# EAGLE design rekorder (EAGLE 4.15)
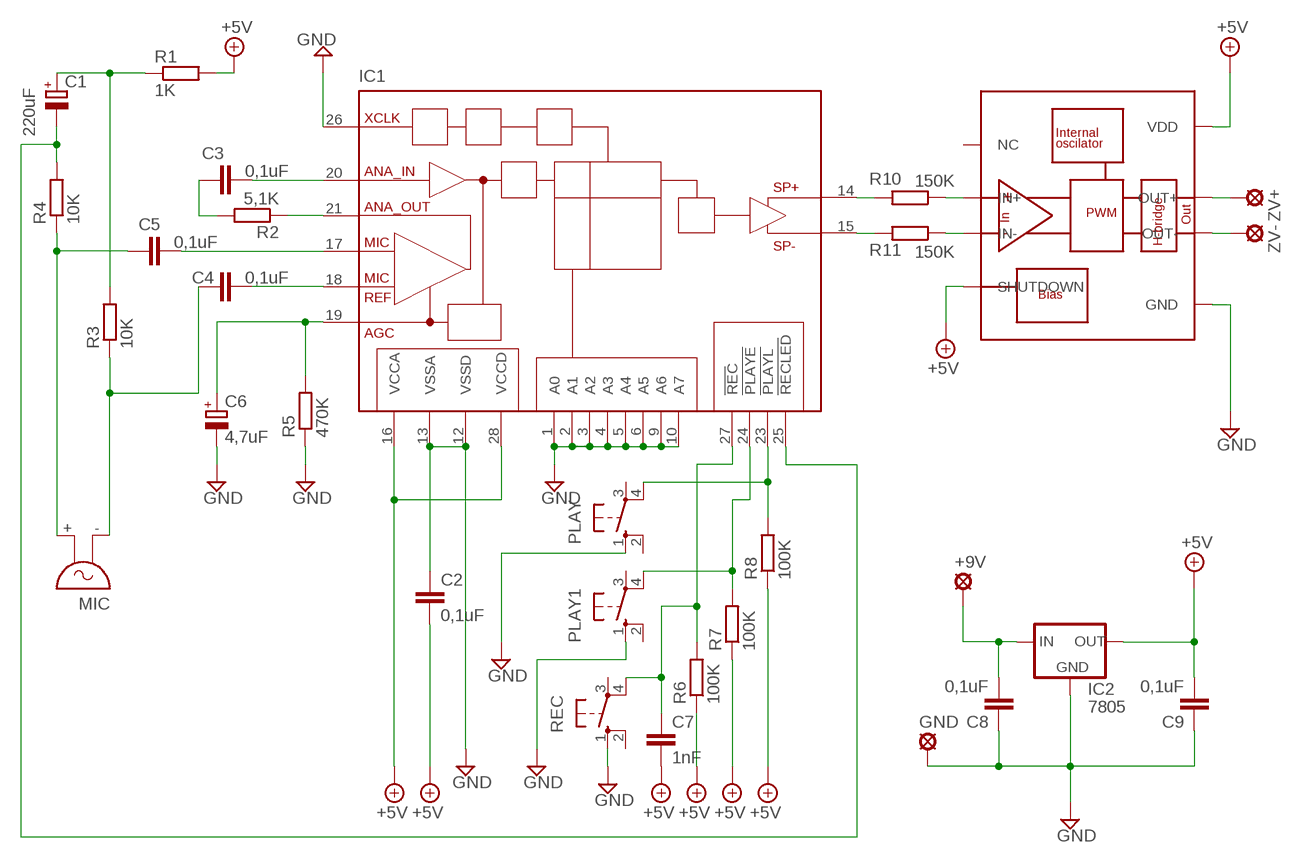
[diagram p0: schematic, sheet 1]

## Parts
+9V  SE13  [SE13]
C1  220uF  CPOL-EUE3.5-8  [E3,5-8]
C2  0,1uF  C-EUC1206  [C1206]
C3  0,1uF  C-EUC1206  [C1206]
C4  0,1uF  C-EUC1206  [C1206]
C5  0,1uF  C-EUC1206  [C1206]
C6  4,7uF  CPOL-EUE2-5  [E2-5]
C7  1nF  C-EUC1206  [C1206]
C8  0,1uF  C-EUC1206  [C1206]
C9  0,1uF  C-EUC1206  [C1206]
GND  SE13  [SE13]
IC1  ISD1400D  [DIL28-6]
IC2  7805  78XXS  [78XXS]
MIC  F/QMX  [F/QMX]
PLAY  10-XX  [B3F-10XX]
PLAY1  10-XX  [B3F-10XX]
R1  1K  R-EU_M1206  [M1206]
R2  5,1K  R-EU_M1206  [M1206]
R3  10K  R-EU_M1206  [M1206]
R4  10K  R-EU_M1206  [M1206]
R5  470K  R-EU_M1206  [M1206]
R6  100K  R-EU_M1206  [M1206]
R7  100K  R-EU_M1206  [M1206]
R8  100K  R-EU_M1206  [M1206]
R10  150K  R-EU_M1206  [M1206]
R11  150K  R-EU_M1206  [M1206]
REC  10-XX  [B3F-10XX]
U$1  TPA2005D1  [8-PIN-QFN]
ZV+  SE13  [SE13]
ZV-  SE13  [SE13]

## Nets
+5V: C2.2 C7.2 C9.2 IC1.16(VCCA) IC1.28(VCCD) IC2.OUT R1.2 R6.1 R7.1 R8.1 U$1.P$1(SHUTDOWN) U$1.P$6(VDD)
GND: C2.1 C6.- C8.1 C9.1 GND.MP IC1.1(A0) IC1.2(A1) IC1.3(A2) IC1.4(A3) IC1.5(A4) IC1.6(A5) IC1.9(A6) IC1.10(A7) IC1.12(VSSD) IC1.13(VSSA) IC1.26(XCLK) IC2.GND PLAY1.1(S) PLAY.1(S) R5.1 REC.1(S) U$1.P$7(GND)
N$1: R10.1 U$1.P$3(IN+)
N$3: IC1.14(SP+) R10.2
N$4: IC1.15(SP-) R11.2
N$5: C1.+ R1.1 R3.2
N$6: IC1.24(PLAYE) PLAY1.4(P1) R7.2
N$7: C7.1 IC1.27(REC) R6.2 REC.4(P1)
N$8: C1.- IC1.25(RECLED) R4.2
N$9: R11.1 U$1.P$4(IN-)
N$10: C3.2 IC1.20(ANA_IN)
N$11: IC1.23(PLAYL) PLAY.4(P1) R8.2
N$12: IC1.21(ANA_OUT) R2.1
N$13: C3.1 R2.2
N$14: C6.+ IC1.19(AGC) R5.2
N$15: U$1.P$5(OUT+) ZV+.MP
N$16: C5.2 IC1.17(MIC)
N$17: C4.2 IC1.18(MIC_REF)
N$18: C5.1 MIC.+ R4.1
N$19: C4.1 MIC.- R3.1
N$20: U$1.P$8(OUT-) ZV-.MP
N$21: +9V.MP C8.2 IC2.IN
Unconnected: IC1.7(NC) IC1.8(NC) IC1.11(NC) IC1.22(NC) PLAY1.2(S1) PLAY1.3(P) PLAY.2(S1) PLAY.3(P) REC.2(S1) REC.3(P) U$1.P$2(NC)

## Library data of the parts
+9V GND ZV+ ZV- = solpad:SE13: SOLDER PAD
C1 C6 = rcl:CPOL-EU: POLARIZED CAPACITOR, European symbol
C2-C5 C7-C9 = rcl:C-EU: CAPACITOR, European symbol
IC1 = isd:ISD1400D: VOICE RECORDER
IC2 = v-reg:78XXS: VOLTAGE REGULATOR
MIC = buzzer:F/QMX: BUZZER
PLAY PLAY1 REC = switch-omron:10-XX: OMRON SWITCH
R1-R8 R10 R11 = rcl:R-EU_: RESISTOR, European symbol
U$1 = texas_pp:TPA2005D1

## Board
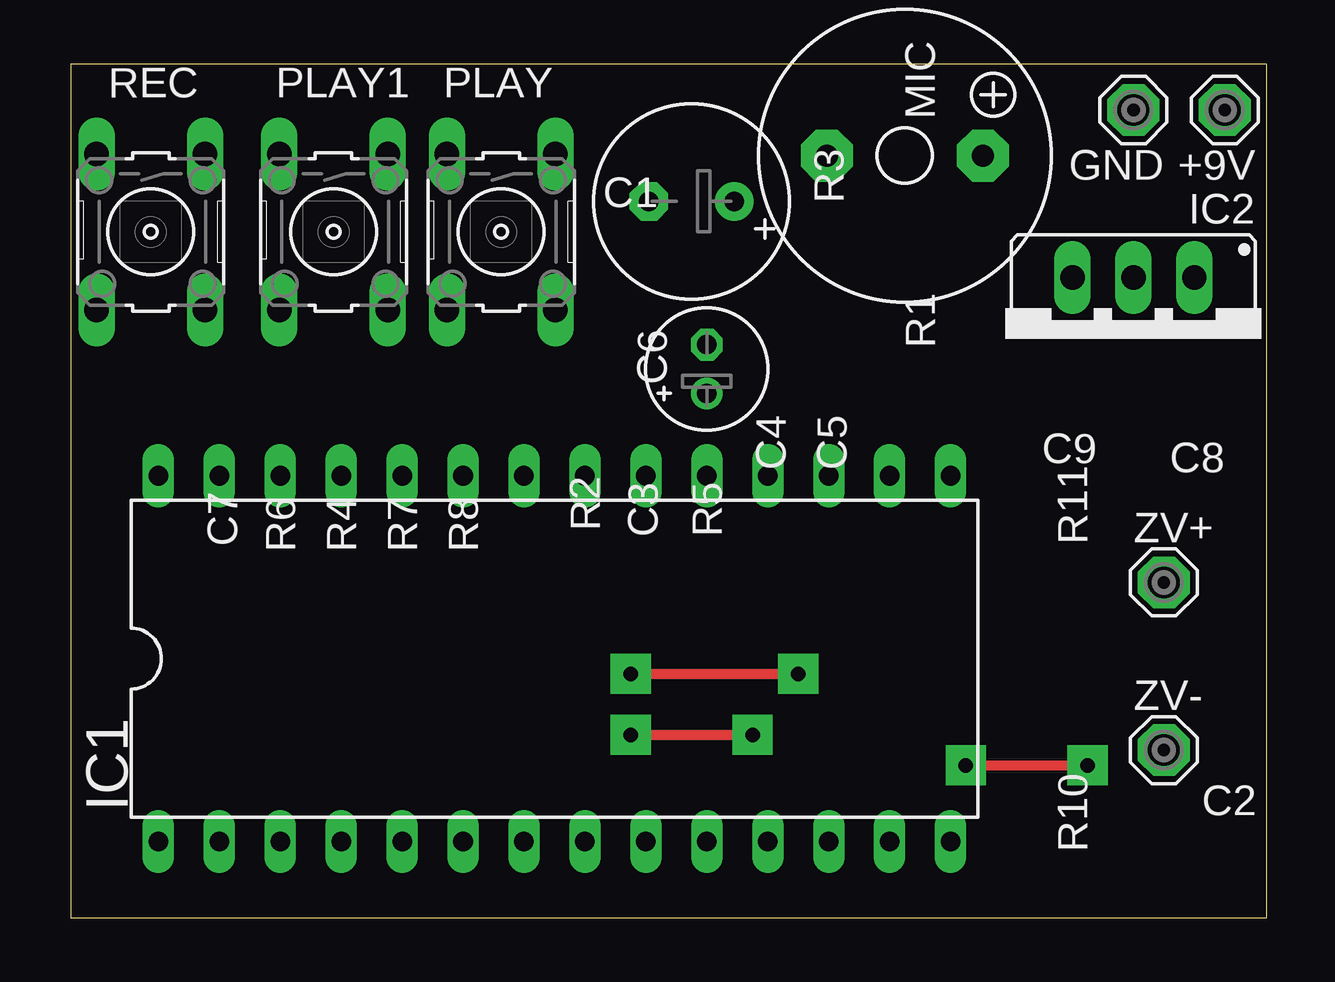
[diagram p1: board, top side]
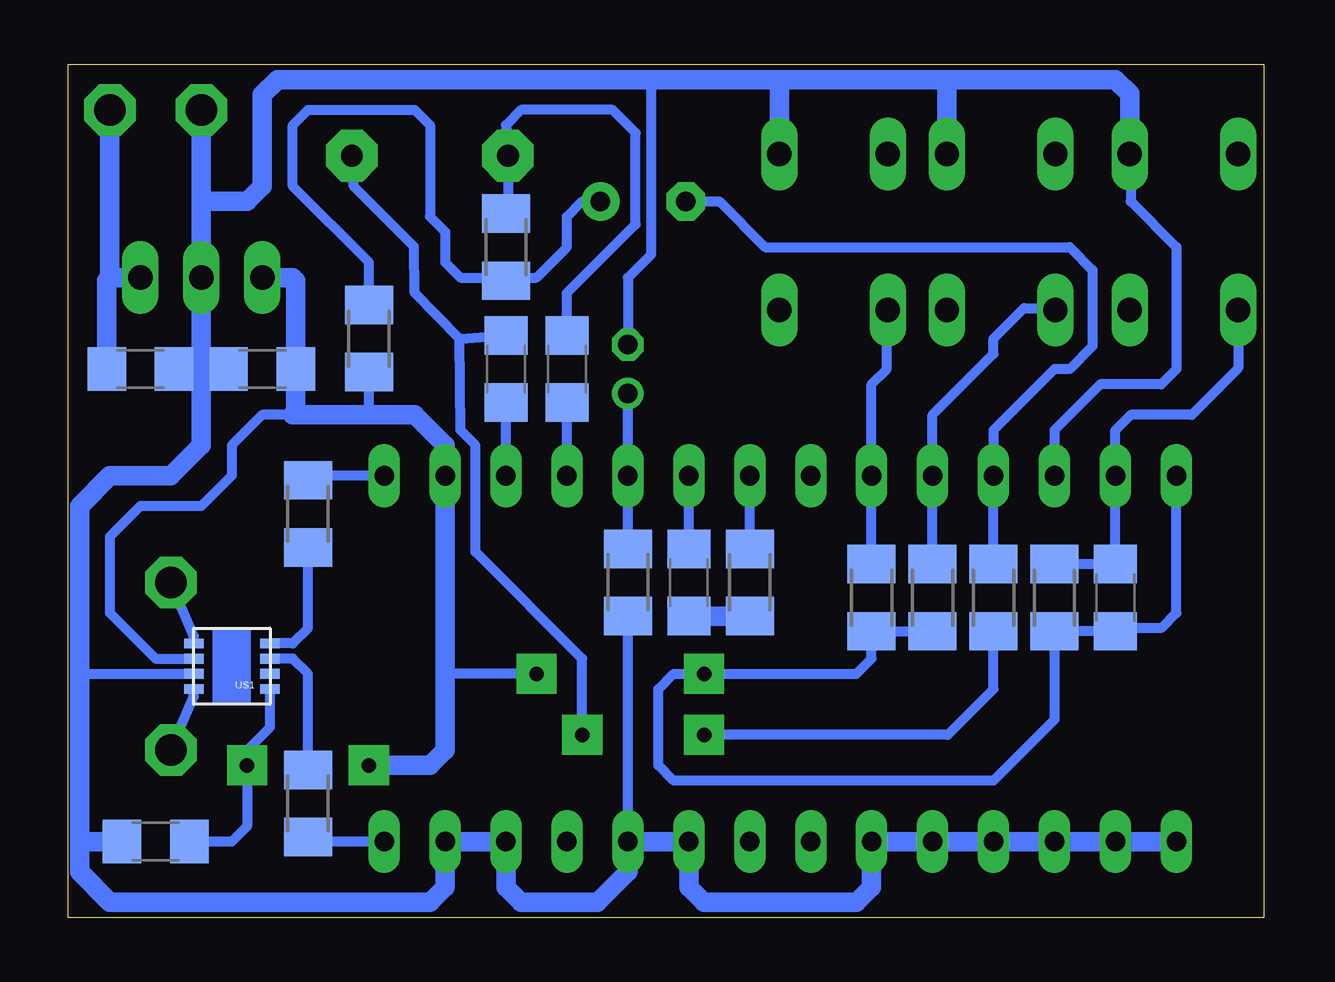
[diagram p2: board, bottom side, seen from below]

Size 49.84 x 35.55 mm. Coordinates in mm from the lower left corner, seen from the top.
Outline: 0,0 49.84,0 49.84,35.55 0,35.55 0,0
Copper layers (1*16): Top 0.035mm / dielectric 1.5mm / Bottom 0.035mm
Design rules "default": minimum track width 10mil, minimum drill 24mil, track to track 8mil, track to pad 8mil, pad to pad 8mil, via to via 8mil, smd to smd 8mil, copper to edge 40mil, drill to drill 8mil, minimum pad ring 10mil, minimum via ring 8mil, stop-mask expansion 4mil, vias tented up to drill 0mil, thermal gap 10mil

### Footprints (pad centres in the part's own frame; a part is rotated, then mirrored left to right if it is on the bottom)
SE13 = drill 1.321 pad 2.159 octagon: MP 0,0
E3,5-8 = drill 0.813 pad 1.6 round: + -1.778,0 | drill 0.813 pad 1.6 octagon: - 1.778,0
C1206 = smd 1.6 x 1.8: 1 -1.4,0; 2 1.4,0
E2-5 = drill 0.813 pad 1.27 round: + -1.016,0 | drill 0.813 pad 1.27 octagon: - 1.016,0
DIL28-6 = drill 0.813 long: 1 -16.51,-7.62; 2 -13.97,-7.62; 3 -11.43,-7.62; 4 -8.89,-7.62; 5 -6.35,-7.62; 6 -3.81,-7.62; 7 -1.27,-7.62; 8 1.27,-7.62; 9 3.81,-7.62; 10 6.35,-7.62; 11 8.89,-7.62; 12 11.43,-7.62; 13 13.97,-7.62; 14 16.51,-7.62; 15 16.51,7.62; 16 13.97,7.62; 17 11.43,7.62; 18 8.89,7.62; 19 6.35,7.62; 20 3.81,7.62; 21 1.27,7.62; 22 -1.27,7.62; 23 -3.81,7.62; 24 -6.35,7.62; 25 -8.89,7.62; 26 -11.43,7.62; 27 -13.97,7.62; 28 -16.51,7.62
78XXS = drill 1.016 long: GND 0,-2.54; IN -2.54,-2.54; OUT 2.54,-2.54
F/QMX = drill 0.914 pad 2.159 octagon: + 3.251,0; - -3.251,0
B3F-10XX = drill 1.016 long: 1 -3.251,2.261; 2 3.251,2.261; 3 -3.251,-2.261; 4 3.251,-2.261
M1206 = smd 1.6 x 2: 1 -1.4,0; 2 1.4,0
8-PIN-QFN = smd 0.813 x 0.406: P$1 -1.587,0.953; P$2 -1.587,0.318; P$3 -1.587,-0.318; P$4 -1.587,-0.953; P$5 1.587,-0.953; P$6 1.587,-0.318; P$7 1.587,0.318; P$8 1.587,0.953

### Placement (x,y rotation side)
+9V  48.1,33.65 180 top
C1  25.87,29.84 180 top
C2  46.19,3.17 0 bottom
C3  23.96,13.96 90 bottom
C4  29.04,22.86 270 bottom
C5  31.58,22.86 270 bottom
C6  26.5,22.86 90 top
C7  6.18,13.33 270 bottom
C8  46.83,22.86 180 bottom
C9  41.75,22.86 0 bottom
GND  44.29,33.65 180 top
IC1  20.15,10.79 0 top
IC2  44.29,24.12 180 top
MIC  34.76,31.75 0 top
PLAY  17.93,28.57 270 top
PLAY1  10.95,28.57 270 top
R1  37.3,24.12 270 bottom
R2  21.43,13.96 270 bottom
R3  31.58,27.94 270 bottom
R4  11.27,13.33 90 bottom
R5  26.5,13.96 90 bottom
R6  8.73,13.33 90 bottom
R7  13.8,13.33 90 bottom
R8  16.34,13.33 90 bottom
R10  39.84,4.76 270 bottom
R11  39.84,16.82 90 bottom
REC  3.33,28.57 270 top
U$1  43.02,10.47 180 bottom
ZV+  45.55,13.96 0 top
ZV-  45.55,6.98 0 top

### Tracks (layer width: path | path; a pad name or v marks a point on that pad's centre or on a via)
+5V  (via drill 0.6 pad 1.68)
  Top 0.406: v37.3,6.35 v42.38,6.35 | v23.33,10.15 v30.32,10.15
  Bottom 0.406: R6.1 9.04,12.06 8.91,11.93 R6.1 | R6.1 C7.2 6.18,12.06 4.28,12.06 3.65,12.7 IC1.28 | 14.12,12.06 13.99,11.93 R7.1 R8.1 | R8.1 16.98,11.74 16.79,11.93 R8.1 | 40.35,26.54 40.48,26.67 | U$1.P$6 46.19,10.79 48.1,12.7 48.1,15.87 46.83,17.14 44.29,17.14 43.02,18.41 43.02,19.68 41.75,20.95 40.48,20.95 40.35,21.08 | U$1.P$1 41.43,7.93 42.38,6.98 v42.38,6.35 42.38,3.81 43.02,3.17 C2.2 44.92,2.54 | v30.32,10.15 34.12,10.15 | R6.1 8.73,8.25 11.27,5.71 24.6,5.71 25.23,6.35 25.23,9.52 24.6,10.15 v23.33,10.15 16.98,10.15 16.34,10.79 R8.1 | R8.1 16.34,12.06 | 36.8,22.73 R1.2 37.3,20.95
  Bottom 0.813: 40.48,26.67 IC2.OUT | 40.35,26.54 C9.2 40.35,21.08 | 40.48,20.95 37.3,20.95 35.4,20.95 34.12,19.68 IC1.16 34.12,10.15 34.12,6.98 34.76,6.35 v37.3,6.35
GND
  Bottom 0.406: 10,34.92 13.21,34.88 | IC1.10 R5.1 | C6.- 26.5,26.67 25.55,27.62 25.55,34.92 | 49.37,10.15 U$1.P$7 | 45.55,0.63 45.69,0.76 | 20.15,34.92 20.19,34.88 | REC.1 5.59,31.78 5.55,31.75 5.55,29.84 3.65,27.94 3.65,22.86 4.28,22.22 6.82,22.22 8.73,20.32 IC1.26
  Bottom 0.813: IC1.1 IC1.2 IC1.3 IC1.4 IC1.5 IC1.6 16.34,1.27 16.98,0.63 23.33,0.63 23.96,1.27 IC1.9 IC1.10 26.5,1.9 27.78,0.63 30.95,0.63 31.58,1.27 IC1.12 IC1.13 34.12,1.27 34.76,0.63 45.55,0.63 48.1,0.63 49.37,1.9 49.37,3.17 | REC.1 5.59,34.32 6.18,34.92 10,34.92 20.15,34.92 25.55,34.92 41.11,34.92 41.75,34.29 41.75,30.48 42.38,29.84 44.29,29.84 | 13.21,34.88 PLAY1.1 | 44.29,29.84 GND.MP | 44.29,29.84 IC2.GND 44.29,22.86 | 49.37,3.17 49.37,10.15 49.37,17.14 48.1,18.41 45.55,18.41 44.29,19.68 44.29,22.86 | 20.19,34.88 PLAY.1 | 44.29,22.86 C9.1 | 44.29,22.86 C8.1 | 49.37,3.17 C2.1
N$1
  Bottom 0.406: R10.1 39.84,10.15 40.48,10.79 U$1.P$3
N$3
  Bottom 0.406: R10.2 39.84,3.17 IC1.14
N$4
  Bottom 0.406: R11.2 39.84,18.41 IC1.15
N$5
  Bottom 0.406: C1.+ 28.41,29.84 29.04,29.21 29.04,27.94 30.32,26.67 31.58,26.67 | R1.1 37.3,27.3 40.48,30.48 40.48,33.02 39.84,33.65 35.4,33.65 34.76,33.02 34.76,29.21 34.12,28.57 34.12,27.3 33.49,26.67 31.58,26.67 | 31.58,26.67 R3.2
N$6
  Bottom 0.406: R7.2 IC1.24 13.8,20.95 11.27,23.49 11.27,24.12 10,25.4 8.73,25.4 PLAY1.4
  Bottom 0.813: R7.2 13.8,14.6
N$7
  Bottom 0.406: R6.2 8.73,14.6 8.59,14.73 C7.1 IC1.27 6.18,20.32 5.55,20.95 3.01,20.95 1.07,22.89 REC.4
  Bottom 0.813: C7.1 6.18,14.6
N$8
  Bottom 0.406: 11.27,14.6 R4.2 IC1.25 11.27,20.32 8.73,22.86 8.09,22.86 7.14,23.81 7.14,26.98 8.09,27.94 20.79,27.94 22.7,29.84 C1.-
N$9
  Bottom 0.406: R11.1 39.84,12.06 40.48,11.42 U$1.P$4
N$10
  Bottom 0.406: 23.96,14.92 C3.2 IC1.20
N$11
  Bottom 0.406: 16.34,14.6 R8.2 IC1.23 16.34,22.22 15.71,22.86 15.71,25.4 15.67,25.36 PLAY.4
N$12
  Bottom 0.406: R2.1 IC1.21
N$13
  Bottom 0.813: C3.1 23.96,12.7 23.83,12.56 R2.2
N$14
  Bottom 0.406: 26.5,14.92 R5.2 IC1.19 C6.+
N$15
  Bottom 0.406: U$1.P$5 44.6,11.74 ZV+.MP
N$16
  Bottom 0.406: IC1.17 C5.2
N$17
  Bottom 0.406: 29.04,21.27 C4.2 IC1.18
N$18  (via drill 0.6 pad 1.68)
  Top 0.406: v23.33,7.62 v28.41,7.62
  Bottom 0.406: 33.51,24.12 33.49,20.32 32.86,19.68 32.86,15.24 28.41,10.79 v28.41,7.62 | 33.51,24.12 33.49,24.12 C5.1 | R4.1 11.27,9.52 13.17,7.62 v23.33,7.62 | 33.51,24.12 35.4,26.03 35.42,27.96 37.94,30.48 MIC.+
N$19
  Bottom 0.406: C4.1 29.04,26.03 26.19,28.89 26.19,32.7 27.14,33.65 30.95,33.65 31.58,33.02 MIC.- 31.51,29.28 31.58,29.21 R3.1
N$20
  Bottom 0.406: U$1.P$8 44.6,9.2 ZV-.MP
N$21
  Bottom 0.406: 48.23,26.54 48.1,26.67
  Bottom 0.813: IC2.IN 48.1,26.67 +9V.MP | C8.2 48.23,26.54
